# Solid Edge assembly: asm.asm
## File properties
Author: Deepak Maini
Template: Normal.asm
Last saved by: MYPC
Revision: 6
Application: Solid Edge
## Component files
plate.par
bolt.par
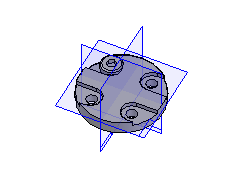
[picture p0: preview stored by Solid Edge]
